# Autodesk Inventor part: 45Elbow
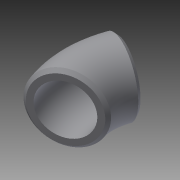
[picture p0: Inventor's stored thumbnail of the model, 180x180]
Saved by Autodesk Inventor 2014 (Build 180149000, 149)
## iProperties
Created: 2004-05
Part Number: 45Elbow
Document SubType Name: Modeling
Designer: dayb
Manufacturer: Standard
Standards Organization: Custom
Density: 1 g/cm^3
Material: Generic
Appearance: Default
Author: dayb
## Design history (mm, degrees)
sketch "Sketch2"
  geometry: L1 (-65.761, 0)-(10.96, 0) reference; L2 (0, 617.551)-(0, -122.409) reference; L3 (0, 0)-(0, 511.842); C1 r 16.701 at (-38.1, 0); C2 r 12.154 at (-38.1, 0)
  constraints: 2 centre point, 2 end point, 2 point on line, 1 coincident
  dimensions: "d14" = 24.3078 diameter of C2 (= ID); "d15" = 33.401 diameter of C1 (= OD); "d17" = 38.1 distance from line of L2 C1.centre (= G)
revolve "Revolution1" sketch "Sketch2" stored, may be unused: angle "d18" = 45 deg
chamfer "Chamfer3" distance "d19" = 1.51553 (= t); stored, may be unused: second distance "d20" = 3.175, angle "d21" = 45 deg
sketch "Sketch4"
  geometry: C1 r 12.154 at (-0.041, 0.006) reference; 2 further points
  constraints: 1 coincident, 1 other
sketch "Sketch5"
  geometry: C1 r 12.154 at (0.041, 0.006) reference; 2 further points
  constraints: 1 coincident, 1 other
body "Solid1"
workpoint "Work Point1"
workaxis "Work Axis1"
workpoint "Work Point2"
workaxis "Work Axis2"
other parameters: "OD" = 33.401 [user parameter; used in 2 equation terms], "ID" = 24.3078 [user parameter; used in 2 equation terms], "G" = 38.1 [user parameter; used in 1 equation term], "t" = 1.51553 (= -0.166667 x ID + 0.166667 x OD) [user parameter; used in 1 equation term]
